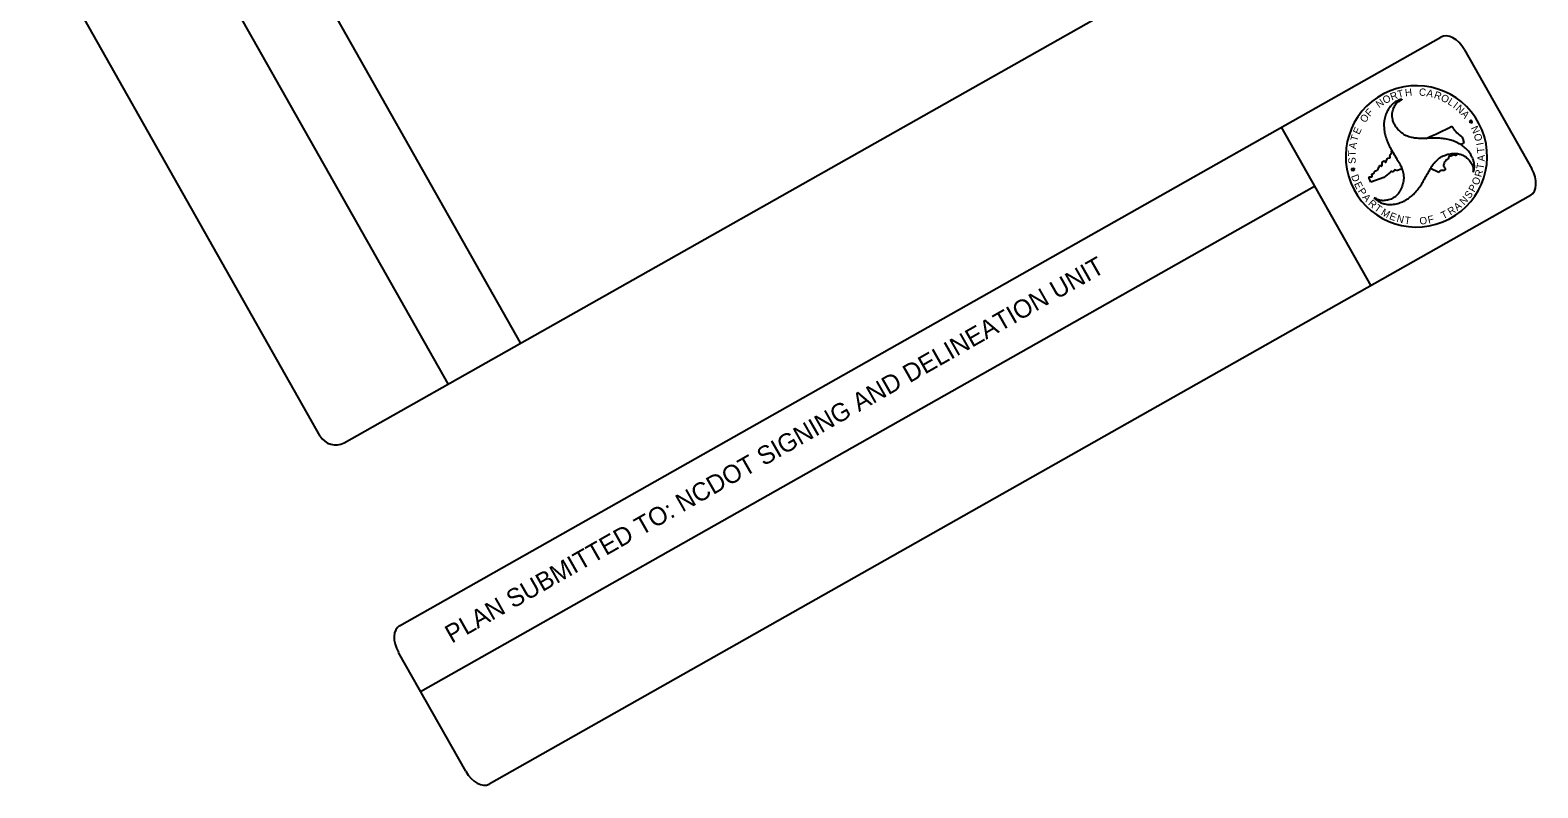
# Model space of a CAD drawing. Extents: x 2217708 to 2219063, y 217550 to 219141.
# Drawn here: x 2217781 to 2218546, y 217550 to 217935 of the extents above; entities that cross this region are included whole.
import ezdxf

# ---------------------------------------------------------------- set-up
doc = ezdxf.new("R2010")
doc.units = 0
doc.layers.add('Default', color=7, linetype='Continuous')
doc.layers.add('Sheet Title CELL', color=7, linetype='Continuous')

msp = doc.modelspace()

# ---------------------------------------------------------------- linework, layer by layer
at = {"layer": 'Default'}
for p, q in [((2218029.66, 217776.18), (2217873.69, 218052.11)), ((2217992.87, 217755.41), (2217858.54, 217992.99)), ((2217968.27, 217632.66), (2218496.55, 217931.46)), ((2218508.46, 217925.01), (2218542.62, 217864.64)), ((2218415.54, 217885.65), (2218461.01, 217805.27)), ((2217978.9, 217599.21), (2218432.39, 217855.86)), ((2218542.01, 217851.09), (2218013.74, 217552.28)), ((2218001.79, 217558.78), (2217967.63, 217619.16))]:
    msp.add_line(p, q, dxfattribs=at)
for centre, major_axis, start_param, end_param in [((2218502.2, 217921.46), (-5.65, 10.01), 4.713091, 6.283887), ((2218536.36, 217861.09), (5.65, -10.01), 0.000702, 1.571498), ((2217973.9, 217622.71), (-5.65, 10.01), 0.000702, 1.571498), ((2218008.06, 217562.33), (5.65, -10.01), 4.713091, 6.283887)]:
    msp.add_ellipse(centre, major_axis=major_axis, ratio=0.62659, start_param=start_param, end_param=end_param, dxfattribs=at)
at = {"layer": 'Sheet Title CELL'}
for p, q in [((2217940.05, 217725.57), (2218420.37, 217996.89)), ((2217927.91, 217728.95), (2217780.8, 217989.42)), ((2218476.75, 217899.9), (2218476.72, 217899.81)), ((2218476.75, 217899.9), (2218476.72, 217899.81)), ((2218511.46, 217888.72), (2218510.87, 217888.48)), ((2218510.87, 217888.48), (2218511.5, 217888.33)), ((2218511.85, 217888.87), (2218511.43, 217889.35)), ((2218511.43, 217889.35), (2218511.46, 217888.72)), ((2218511.5, 217888.33), (2218511.56, 217887.68)), ((2218511.56, 217887.68), (2218511.88, 217888.22)), ((2218512.43, 217889.13), (2218511.85, 217888.87)), ((2218511.88, 217888.22), (2218512.51, 217888.06)), ((2218512.1, 217888.57), (2218512.43, 217889.13)), ((2218512.51, 217888.06), (2218512.1, 217888.57)), ((2218489.05, 217880.06), (2218489.05, 217880.06)), ((2218451.09, 217864.21), (2218451.7, 217864.46)), ((2218451.72, 217864.05), (2218451.09, 217864.21)), ((2218451.7, 217864.46), (2218451.64, 217865.08)), ((2218451.64, 217865.08), (2218452.07, 217864.61)), ((2218451.78, 217863.4), (2218451.72, 217864.05)), ((2218452.09, 217863.95), (2218451.78, 217863.4)), ((2218452.07, 217864.61), (2218452.67, 217864.85)), ((2218452.73, 217863.79), (2218452.09, 217863.95)), ((2218452.67, 217864.85), (2218452.32, 217864.29)), ((2218452.32, 217864.29), (2218452.73, 217863.79)), ((2218476.83, 217864.64), (2218474.07, 217863.56)), ((2218495.43, 217862.75), (2218491.25, 217864.74)), ((2218491.25, 217864.74), (2218491.25, 217864.74)), ((2218460.97, 217857.79), (2218460.2, 217859.91)), ((2218467.66, 217860.19), (2218460.97, 217857.79)), ((2218470.99, 217862.83), (2218467.66, 217860.19))]:
    msp.add_line(p, q, dxfattribs=at)
for centre, radius, start, end in [((2218484.14, 217870.9), 35.88, 21.90467, 201.90467), ((2218484.14, 217870.9), 35.88, 201.90467, 21.90467), ((2218411.84, 218061.75), 197.41, 293.02221, 297.22822), ((2218411.84, 218061.75), 197.41, 287.58316, 287.68275), ((2217935.67, 217733.33), 8.91, 209.45694, 299.45694)]:
    msp.add_arc(centre, radius, start, end, dxfattribs=at)
for points in [[(2218476.72, 217899.81), (2218475.85, 217899.7), (2218473.58, 217898.68), (2218471.54, 217896.98), (2218471.38, 217896.79), (2218470.45, 217895.7), (2218469.58, 217894.27), (2218468.41, 217891.73), (2218467.85, 217888.96), (2218467.65, 217887.79), (2218467.69, 217886.46), (2218467.91, 217883.7), (2218468.46, 217881.17), (2218469.42, 217878.34), (2218470.43, 217875.93), (2218471.83, 217873.61), (2218473.27, 217871.28), (2218474.61, 217868.99), (2218475.96, 217866.63), (2218476.96, 217864.15), (2218477.04, 217863.93), (2218477.66, 217861.11), (2218477.52, 217858.36), (2218476.93, 217855.86), (2218476.47, 217854.64), (2218475.67, 217853.26), (2218475.23, 217852.47), (2218473.97, 217851.04), (2218471.82, 217849.52), (2218469.44, 217848.72), (2218467.17, 217848.42), (2218464.89, 217848.85), (2218462.78, 217849.95)], [(2218512.95, 217862.83), (2218513.26, 217863.6), (2218513.53, 217866.09), (2218513.08, 217868.71), (2218513.02, 217868.96), (2218512.51, 217870.3), (2218511.71, 217871.78), (2218510.12, 217874.07), (2218507.97, 217875.92), (2218507.08, 217876.69), (2218505.89, 217877.33), (2218503.4, 217878.51), (2218500.94, 217879.31), (2218498.01, 217879.87), (2218495.41, 217880.18), (2218492.68, 217880.16), (2218489.96, 217880.07), (2218487.34, 217880.06), (2218484.57, 217880.07), (2218481.95, 217880.44), (2218481.72, 217880.5), (2218478.93, 217881.37), (2218476.63, 217882.87), (2218474.75, 217884.61), (2218473.96, 217885.62), (2218473.17, 217887.01), (2218472.67, 217887.8), (2218472.09, 217889.6), (2218471.84, 217892.24), (2218472.34, 217894.67), (2218473.22, 217896.78), (2218474.75, 217898.55), (2218476.72, 217899.81), (2218476.75, 217899.9)], [(2218506.67, 217876.96), (2218505.89, 217877.33), (2218503.4, 217878.51), (2218500.94, 217879.31), (2218498.01, 217879.87), (2218495.41, 217880.18), (2218492.68, 217880.16), (2218489.96, 217880.07), (2218489.05, 217880.06)], [(2218502.16, 217886.21), (2218503.59, 217884.09), (2218505.9, 217881.85), (2218507.28, 217880.67), (2218507.78, 217879.38), (2218508.1, 217877.72), (2218506.68, 217876.97)], [(2218460.2, 217859.91), (2218460.05, 217860.08), (2218460.31, 217860.45), (2218461.45, 217860.44), (2218461.77, 217861.06), (2218461.58, 217861.47), (2218461.8, 217862.05), (2218462.53, 217862.19), (2218462.82, 217863.2), (2218463.33, 217863.56), (2218464.5, 217864.03), (2218465.33, 217865.99), (2218465.88, 217866.31), (2218466.17, 217866), (2218466.56, 217866.07), (2218466.7, 217867.46), (2218466.79, 217867.69), (2218467.7, 217868.56), (2218468.07, 217868.47), (2218468.36, 217867.99), (2218468.56, 217867.95), (2218468.82, 217868.35), (2218469.05, 217869.16), (2218469.76, 217869.99), (2218470.83, 217870.27), (2218470.67, 217871.18), (2218471.54, 217872.46), (2218471.59, 217873.04), (2218471.46, 217873.56)], [(2218462.78, 217849.95), (2218463.35, 217849.26), (2218465.36, 217847.8), (2218467.84, 217846.86), (2218468.08, 217846.83), (2218469.51, 217846.56), (2218471.18, 217846.54), (2218473.97, 217846.78), (2218476.62, 217847.7), (2218477.74, 217848.09), (2218478.92, 217848.82), (2218481.14, 217850.37), (2218483.06, 217852.08), (2218485.04, 217854.35), (2218486.6, 217856.42), (2218487.94, 217858.82), (2218489.21, 217861.23), (2218490.54, 217863.52), (2218491.93, 217865.86), (2218493.55, 217867.99), (2218493.75, 217868.18), (2218495.89, 217870.13), (2218498.31, 217871.37), (2218500.74, 217872.11), (2218502.07, 217872.34), (2218503.63, 217872.29), (2218504.58, 217872.35), (2218506.42, 217871.95), (2218508.8, 217870.84), (2218510.67, 217869.2), (2218512.08, 217867.36), (2218512.85, 217865.17), (2218512.95, 217862.83)], [(2218471.8, 217873.67), (2218471.83, 217873.61), (2218473.27, 217871.28), (2218474.61, 217868.99), (2218475.96, 217866.63), (2218476.82, 217864.63)], [(2218491.25, 217864.74), (2218491.93, 217865.86), (2218493.55, 217867.99), (2218493.75, 217868.18), (2218495.89, 217870.13), (2218498.31, 217871.37), (2218500.74, 217872.11), (2218502.07, 217872.34), (2218503.63, 217872.29), (2218504.51, 217872.33)], [(2218504.5, 217872.32), (2218504.43, 217871.58), (2218503.92, 217871.33), (2218502.71, 217871.69), (2218501.68, 217871.02), (2218501.04, 217871.11), (2218500.7, 217870.98), (2218500.3, 217869.63), (2218499.28, 217868.94), (2218498.02, 217866.89), (2218497.96, 217865.97), (2218498.76, 217864.35), (2218498.45, 217863.84), (2218497.88, 217863.71), (2218496.6, 217863.7), (2218495.43, 217862.75)], [(2218474.07, 217863.56), (2218473.6, 217863.96), (2218473, 217863.9), (2218472.43, 217863.23), (2218471.87, 217863.04), (2218471.1, 217863.23), (2218470.99, 217862.83)]]:
    msp.add_spline(points, degree=3, dxfattribs=at)

# ---------------------------------------------------------------- texts
at = {"layer": 'Default'}
msp.add_text('PLAN SUBMITTED TO: NCDOT SIGNING AND DELINEATION UNIT', height=9.2466, rotation=29.63919, dxfattribs=at).set_placement((2217994.68, 217623.51))
at = {"layer": 'Sheet Title CELL'}
for s, height, rotation, p in [('R', 3.73, 20.7804, (2218471.66, 217899.21)), ('T', 3.74, 14.13077, (2218475, 217900.48)), ('H', 3.73, 7.04605, (2218478.55, 217901.34)), ('C', 3.72, 354.7037, (2218485.29, 217901.83)), ('A', 3.73, 347.20667, (2218489, 217901.47)), ('R', 3.73, 340.84273, (2218492.74, 217900.63)), ('O', 3.74, 333.72312, (2218496.11, 217899.44)), ('F', 3.74, 46.97538, (2218460.46, 217890.82)), ('N', 3.73, 34.88844, (2218465.15, 217895.32)), ('O', 3.74, 27.39033, (2218468.16, 217897.39)), ('L', 3.72, 327.48945, (2218499.68, 217897.69)), ('I', 3.74, 323.5001, (2218502.36, 217895.89)), ('N', 3.73, 317.8, (2218503.81, 217894.79)), ('O', 3.74, 54.12222, (2218458.13, 217887.63)), ('A', 3.73, 310.36802, (2218506.5, 217892.31)), ('T', 3.72, 73.17723, (2218454.08, 217878.23)), ('E', 3.72, 66.0616, (2218455.15, 217881.72)), ('N', 3.73, 114.1128, (2218516.46, 217883.57)), ('O', 3.72, 106.86478, (2218517.81, 217879.27)), ('T', 3.74, 87.28476, (2218453.2, 217870.78)), ('A', 3.75, 80.23245, (2218453.42, 217874.42)), ('I', 3.74, 101.72915, (2218518.32, 217876.93)), ('T', 3.73, 96.07925, (2218518.79, 217872.74)), ('A', 3.74, 88.99482, (2218518.76, 217868.31)), ('S', 3.73, 93.66092, (2218453.42, 217867.23)), ('R', 3.74, 74.80799, (2218517.12, 217860.12)), ('T', 3.72, 80.90778, (2218518.16, 217864.12)), ('D', 3.73, 289.75766, (2218450.91, 217860.96)), ('E', 3.72, 296.04555, (2218452.4, 217856.94)), ('P', 3.73, 60.92689, (2218513.52, 217852.43)), ('O', 3.74, 67.61888, (2218515.43, 217855.94)), ('P', 3.73, 303.57795, (2218454.25, 217853.33)), ('A', 3.73, 310.17052, (2218456.46, 217850.01)), ('R', 3.73, 317.23916, (2218459.34, 217846.66)), ('N', 3.72, 46.52457, (2218508.25, 217845.97)), ('S', 3.72, 53.73504, (2218511.1, 217849.08)), ('T', 3.73, 323.88969, (2218462.4, 217843.89)), ('M', 3.72, 331.12473, (2218465.86, 217841.44)), ('E', 3.72, 338.5915, (2218470.05, 217839.22)), ('N', 3.74, 345.56305, (2218473.82, 217837.79)), ('F', 3.73, 12.87396, (2218490.34, 217836.77)), ('T', 3.72, 25.78319, (2218497.66, 217838.95)), ('R', 3.74, 32.73981, (2218501.45, 217840.83)), ('A', 3.72, 39.49294, (2218504.89, 217843.11)), ('T', 3.73, 352.40505, (2218477.91, 217836.78)), ('O', 3.73, 5.70873, (2218485.86, 217836.26))]:
    msp.add_text(s, height=height, rotation=rotation, dxfattribs=at).set_placement(p)

doc.saveas('drawing.dxf')
